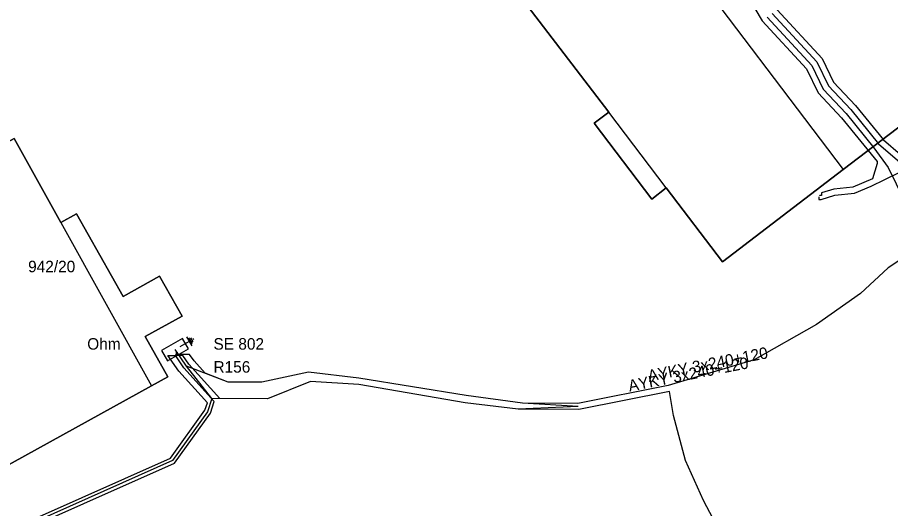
# Model space of a CAD drawing. Extents: x -793400 to -756198, y -1074141 to -1042963.
# Drawn here: x -783099 to -783042.2, y -1065192.2 to -1065160.3 of the extents above; entities that cross this region are included whole.
import ezdxf

# ---------------------------------------------------------------- set-up
doc = ezdxf.new("R2010")
doc.units = 0
for name, color, linetype in [('Parcela', 7, 'Continuous'), ('Popiskový text - Parcela', 7, 'Continuous'), ('Popiskový text - Rozpojovací skříň nn - SJZ', 7, 'Continuous'), ('Popiskový text - Rozpojovací skříň nn - Typ', 7, 'Continuous'), ('Popiskový text - Uzemnění - Odpor', 7, 'Continuous'), ('Popiskový text - Vedení nn kabelové', 7, 'Continuous'), ('Skříň', 7, 'Continuous'), ('Spojnice nn', 7, 'Continuous'), ('Stavební objekt', 7, 'Continuous'), ('Uzemnění', 7, 'Continuous'), ('Vedení nn kabelové', 7, 'Continuous')]:
    doc.layers.add(name, color=color, linetype=linetype)

msp = doc.modelspace()

# ---------------------------------------------------------------- linework, layer by layer
at = {"layer": 'Parcela'}
for points in [[(-783062.82, -1065130.68), (-783065.38, -1065126.9), (-783070.16, -1065121.07), (-783078.17, -1065126.78), (-783086.05, -1065132.94), (-783082.37, -1065137.77), (-783083.31, -1065138.48), (-783079.56, -1065143.43), (-783078.61, -1065142.71), (-783071.47, -1065152.1), (-783072.41, -1065152.82), (-783068.64, -1065157.77), (-783067.7, -1065157.05), (-783060.55, -1065166.44), (-783061.49, -1065167.16), (-783057.74, -1065172.09), (-783056.8, -1065171.37), (-783053.14, -1065176.18), (-783045.29, -1065170.16), (-783037.3, -1065164.1)], [(-783062.82, -1065130.68), (-783037.3, -1065164.1), (-783045.29, -1065170.16), (-783053.14, -1065176.18), (-783056.8, -1065171.37), (-783057.74, -1065172.09), (-783061.49, -1065167.16), (-783060.55, -1065166.44), (-783067.7, -1065157.05), (-783068.64, -1065157.77), (-783072.41, -1065152.82), (-783071.47, -1065152.1), (-783078.61, -1065142.71), (-783079.56, -1065143.43), (-783083.31, -1065138.48), (-783082.37, -1065137.77), (-783086.05, -1065132.94), (-783078.17, -1065126.78), (-783070.16, -1065121.07), (-783065.38, -1065126.9)], [(-783099.26, -1065168.14), (-783096.22, -1065173.62), (-783095.19, -1065173.05), (-783092.17, -1065178.43), (-783089.79, -1065177.11), (-783088.33, -1065179.73), (-783090.72, -1065181.05), (-783089.26, -1065183.68), (-783090.31, -1065184.26), (-783103.53, -1065191.55), (-783106.44, -1065186.28), (-783107.49, -1065186.86), (-783110.46, -1065181.42), (-783109.43, -1065180.85), (-783112.44, -1065175.39)], [(-783099.26, -1065168.14), (-783112.44, -1065175.39), (-783109.43, -1065180.85), (-783110.46, -1065181.42), (-783107.49, -1065186.86), (-783106.44, -1065186.28), (-783103.53, -1065191.55), (-783090.31, -1065184.26), (-783089.26, -1065183.68), (-783090.72, -1065181.05), (-783088.33, -1065179.73), (-783089.79, -1065177.11), (-783092.17, -1065178.43), (-783095.19, -1065173.05), (-783096.22, -1065173.62)]]:
    msp.add_lwpolyline(points, close=True, dxfattribs=at)
at = {"layer": 'Skříň'}
msp.add_lwpolyline([(-783088.292, -1065181.167), (-783089.659, -1065181.95), (-783089.268, -1065182.633), (-783087.901, -1065181.85)], close=True, dxfattribs=at)
at = {"layer": 'Spojnice nn'}
for p, q in [((-783088.04, -1065182.97), (-783088.78, -1065181.9)), ((-783086.38, -1065185.09), (-783088.04, -1065182.97)), ((-783088.94, -1065189.13), (-783106.46, -1065196.91))]:
    msp.add_line(p, q, dxfattribs=at)
for points in [[(-783062.53, -1065185.6), (-783066.17, -1065185.38), (-783069.84, -1065184.89), (-783076.81, -1065183.76), (-783080.1, -1065183.36), (-783083.14, -1065184.02), (-783085.32, -1065184.01), (-783088.04, -1065182.97)], [(-783062.53, -1065185.6), (-783066.45, -1065185.78), (-783069.9, -1065185.36), (-783076.81, -1065184.17), (-783079.96, -1065183.98), (-783082.77, -1065185.1), (-783086.38, -1065185.09)], [(-783086.38, -1065185.09), (-783086.66, -1065185.94), (-783088.94, -1065189.13)]]:
    msp.add_lwpolyline(points, dxfattribs=at)
at = {"layer": 'Stavební objekt'}
for points in [[(-783045.29, -1065170.16), (-783053.14, -1065176.18), (-783056.8, -1065171.37), (-783060.55, -1065166.44), (-783067.7, -1065157.05), (-783071.47, -1065152.1), (-783078.61, -1065142.71), (-783082.37, -1065137.77), (-783086.05, -1065132.94), (-783078.17, -1065126.78)], [(-783090.31, -1065184.26), (-783103.53, -1065191.55), (-783106.44, -1065186.28), (-783109.43, -1065180.85), (-783112.44, -1065175.39), (-783099.26, -1065168.14), (-783096.22, -1065173.62)]]:
    msp.add_lwpolyline(points, close=True, dxfattribs=at)
at = {"layer": 'Uzemnění'}
for p, q in [((-783087.674, -1065181.657), (-783088.021, -1065181.06)), ((-783088.44, -1065181.702), (-783087.847, -1065181.358)), ((-783087.657, -1065181.503), (-783087.878, -1065181.122)), ((-783087.609, -1065181.387), (-783087.752, -1065181.14)), ((-783087.563, -1065181.253), (-783087.613, -1065181.167))]:
    msp.add_line(p, q, dxfattribs=at)
at = {"layer": 'Vedení nn kabelové'}
for points in [[(-783051.033, -1065159.685), (-783050.552, -1065160.491), (-783047.664, -1065163.618), (-783046.914, -1065165.169), (-783045.392, -1065166.793), (-783043.072, -1065169.654), (-783043.069, -1065169.778), (-783043.38, -1065170.78), (-783044.65, -1065171.31), (-783045.9, -1065171.44), (-783046.692, -1065171.689), (-783046.692, -1065171.864), (-783046.808, -1065171.864), (-783046.808, -1065171.85)], [(-783049.908, -1065160.009), (-783046.996, -1065163.162), (-783046.247, -1065164.711), (-783044.788, -1065166.267), (-783042.979, -1065168.498), (-783040.68, -1065170.47)], [(-783049.586, -1065159.768), (-783046.662, -1065162.934), (-783045.913, -1065164.482), (-783044.487, -1065166.004), (-783042.669, -1065168.246), (-783040.446, -1065170.146)], [(-783050.23, -1065160.25), (-783047.33, -1065163.39), (-783046.58, -1065164.94), (-783045.09, -1065166.53), (-783043.29, -1065168.75), (-783042.35, -1065170.04), (-783040.3, -1065174.25)], [(-783046.858, -1065171.938), (-783046.858, -1065172.117), (-783046.72, -1065172.117), (-783045.819, -1065171.834), (-783044.55, -1065171.702), (-783043.466, -1065171.249), (-783041.69, -1065170.38)], [(-783040.39, -1065175.27), (-783042.35, -1065176.58), (-783044.15, -1065178.24), (-783047.03, -1065180.27), (-783051.08, -1065182.57), (-783056.669, -1065184.244), (-783062.569, -1065185.404), (-783066.17, -1065185.38), (-783069.84, -1065184.89), (-783076.81, -1065183.76), (-783080.1, -1065183.36), (-783083.14, -1065184.02), (-783085.32, -1065184.01), (-783086.823, -1065183.435), (-783087.547, -1065182.629), (-783087.836, -1065182.21), (-783088.696, -1065182.21), (-783088.696, -1065182.063)], [(-783106.559, -1065196.735), (-783089.071, -1065188.969), (-783086.84, -1065185.849), (-783086.679, -1065185.357), (-783088.534, -1065183.311), (-783089.247, -1065182.28), (-783088.672, -1065182.28), (-783088.672, -1065182.063)], [(-783106.361, -1065197.085), (-783088.809, -1065189.291), (-783086.48, -1065186.032), (-783086.232, -1065185.279), (-783088.204, -1065183.084), (-783088.786, -1065182.243), (-783088.622, -1065182.243), (-783088.622, -1065182.063)], [(-783052.07, -1065196.09), (-783054.38, -1065191.72), (-783055.55, -1065189.12), (-783056.34, -1065186.19), (-783056.597, -1065184.637), (-783062.491, -1065185.796), (-783066.45, -1065185.78), (-783069.9, -1065185.36), (-783076.81, -1065184.17), (-783079.96, -1065183.98), (-783082.77, -1065185.1), (-783085.871, -1065185.091), (-783087.875, -1065182.856), (-783088.274, -1065182.28), (-783088.647, -1065182.28), (-783088.647, -1065182.213), (-783088.647, -1065182.063)]]:
    msp.add_lwpolyline(points, dxfattribs=at)

# ---------------------------------------------------------------- texts
at = {"layer": 'Popiskový text - Parcela'}
msp.add_text('942/20', height=0.75, dxfattribs=at).set_placement((-783098.349, -1065176.862))
at = {"layer": 'Popiskový text - Rozpojovací skříň nn - SJZ'}
msp.add_text('R156', height=0.75, dxfattribs=at).set_placement((-783086.28, -1065183.4))
at = {"layer": 'Popiskový text - Rozpojovací skříň nn - Typ'}
msp.add_text('SE 802', height=0.75, dxfattribs=at).set_placement((-783086.28, -1065181.9))
at = {"layer": 'Popiskový text - Uzemnění - Odpor'}
msp.add_text(' Ohm', height=0.75, dxfattribs=at).set_placement((-783094.78, -1065181.9))
at = {"layer": 'Popiskový text - Vedení nn kabelové'}
for p in [(-783057.928, -1065183.982), (-783059.195, -1065184.638)]:
    msp.add_text('AYKY 3x240+120', height=0.75, rotation=11.1154, dxfattribs=at).set_placement(p)

doc.saveas('drawing.dxf')
